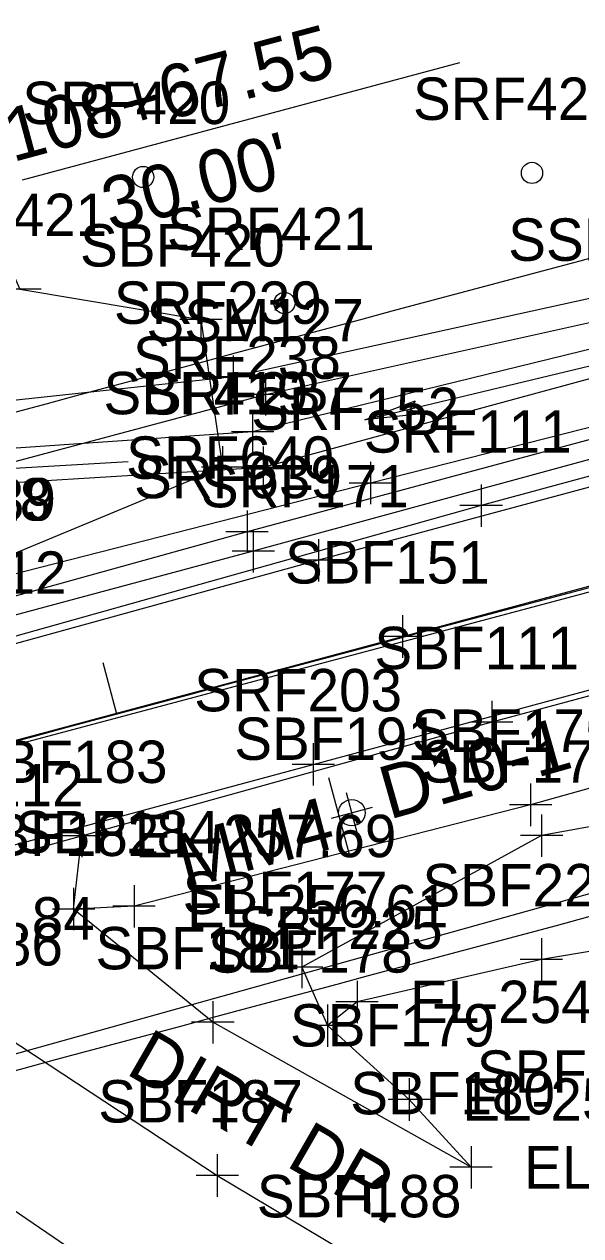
# Model space of a CAD drawing. Extents: x 818717 to 846077, y 440014 to 541392.
# Drawn here: x 831821.7 to 831874.2, y 493090.2 to 493204.5 of the extents above; entities that cross this region are included whole.
import ezdxf

# ---------------------------------------------------------------- set-up
doc = ezdxf.new("R2010")
doc.units = 0
for name, color, linetype in [('SURVEY - CENTERLINE - Preliminary', 7, 'Continuous'), ('SURVEY - CENTERLINE - Preliminary Text', 7, 'Continuous'), ('SURVEY - DRAINAGE - Area Shapes', 7, 'Continuous'), ('SURVEY - DRAINAGE - Natural Features Text', 7, 'Continuous'), ('SURVEY - DTM - Breaklines', 7, 'Continuous'), ('SURVEY - DTM - Breaklines - Points - Elevations', 7, 'Continuous'), ('SURVEY - DTM - Breaklines - Points - Locators', 7, 'Continuous'), ('SURVEY - DTM - Breaklines - Points - Numbers', 7, 'Continuous'), ('SURVEY - DTM - Spot Points - Locators', 7, 'Continuous'), ('SURVEY - DTM - Spot Points - Point Numbers', 7, 'Continuous'), ('SURVEY - PROPERTY - ROW Lines', 7, 'Continuous'), ('SURVEY - PROPERTY - Station and Offset Flags', 7, 'Continuous'), ('SURVEY - TRAFFIC CONTROL - Pavement Marking - Points - Locators', 7, 'Continuous'), ('SURVEY - TRAFFIC CONTROL - Pavement Marking - Points - Numbers', 7, 'Continuous'), ('SURVEY - TRAFFIC CONTROL - Pavement Marking with Text', 7, 'Continuous'), ('SURVEY - TRAFFIC CONTROL - Signs - Points - Locators', 7, 'Continuous'), ('SURVEY - TRAFFIC CONTROL - Signs - Points - Numbers', 7, 'Continuous'), ('SURVEY - TRAFFIC CONTROL - Signs and Devices with Text', 7, 'Continuous'), ('SURVEY - TRANSPORTATION - Features', 7, 'Continuous'), ('SURVEY - TRANSPORTATION - Features - Points - Elevations', 7, 'Continuous'), ('SURVEY - TRANSPORTATION - Features - Points - Locators', 7, 'Continuous'), ('SURVEY - TRANSPORTATION - Features - Points - Numbers', 7, 'Continuous'), ('SURVEY - TRANSPORTATION - Features Text', 7, 'Continuous'), ('SURVEY - TRANSPORTATION - Roads', 7, 'Continuous'), ('SURVEY - TRANSPORTATION - Roads - Points - Locators', 7, 'Continuous'), ('SURVEY - TRANSPORTATION - Roads - Points - Numbers', 7, 'Continuous'), ('SURVEY - UTILITIES - Electric (Overhead) with Text', 7, 'Continuous'), ('SURVEY - UTILITIES - Telephone (Underground) - Points - Locators', 7, 'Continuous'), ('SURVEY - UTILITIES - Telephone (Underground) - Points - Numbers', 7, 'Continuous'), ('SURVEY - UTILITIES - Telephone (Underground) with Text', 7, 'Continuous'), ('SURVEY - UTILITIES - Water - Points - Locators', 7, 'Continuous'), ('SURVEY - UTILITIES - Water - Points - Numbers', 7, 'Continuous'), ('SURVEY - UTILITIES - Water with Text', 7, 'Continuous'), ('SURVEY - VEGETATION - Features - Points - Locators', 7, 'Continuous'), ('SURVEY - VEGETATION - Features - Points - Numbers', 7, 'Continuous'), ('SURVEY - VEGETATION - Features with Text', 7, 'Continuous')]:
    doc.layers.add(name, color=color, linetype=linetype)

msp = doc.modelspace()

# ---------------------------------------------------------------- linework, layer by layer
at = {"layer": 'SURVEY - CENTERLINE - Preliminary'}
msp.add_arc((846074.62, 440015.93), 55000, 104.635499, 105.043654, dxfattribs=at)
msp.add_arc((846074.62, 440015.93), 55000, 104.635499, 105.043654, dxfattribs=at)
msp.add_arc((846074.62, 440015.93), 55000, 104.635499, 105.043654, dxfattribs=at)
at = {"layer": 'SURVEY - CENTERLINE - Preliminary Text'}
msp.add_line((831830.44, 493139.41), (831829.15, 493144.24), dxfattribs=at)
at = {"layer": 'SURVEY - DRAINAGE - Area Shapes'}
msp.add_lwpolyline([(833331.86, 493535.43), (832825.85, 493400.54), (832121.68, 493216.64), (831495.16, 493049.75), (830960.37, 492909.24), (830124.73, 492686.08), (830069.9, 493396.23), (830870.86, 494031.84), (831248.11, 494413.67), (831536.95, 494545.33), (832050.07, 494534.01), (832097.96, 494614.84), (832139.36, 494784.62), (832167.46, 494840.58), (832274.31, 494844.36), (832647.22, 494804.13), (832934.24, 494910.41), (833081.03, 494456.05), (833331.86, 493535.43)], dxfattribs=at)
at = {"layer": 'SURVEY - DRAINAGE - Natural Features Text'}
for p, q in [((831853.84, 493167.16), (831891.8, 493176.31)), ((831856.46, 493167.79), (831853.84, 493167.16)), ((831800.97, 493161.51), (831831.51, 493163.23))]:
    msp.add_line(p, q, dxfattribs=at)
msp.add_lwpolyline([(831853.84, 493167.16), (831858.6, 493168.97), (831858.12, 493168.19), (831858.9, 493167.71)], close=True, dxfattribs=at)
msp.add_lwpolyline([(831853.84, 493167.16), (831858.6, 493168.97), (831858.12, 493168.19), (831858.9, 493167.71), (831853.84, 493167.16)], dxfattribs=at)
at = {"layer": 'SURVEY - DTM - Breaklines'}
for points in [[(831770.96, 493123.4), (831813.86, 493135.07), (831857.39, 493146.73), (831900.86, 493158.47), (831946.48, 493170.59), (831992.71, 493182.98), (832039.15, 493195.18), (832084.76, 493206.97), (832129.99, 493218.78), (832149.29, 493223.98), (832194.39, 493235.62), (832247.61, 493249.75), (832293.49, 493261.68), (832340.52, 493273.78)], [(832142.59, 493248.12), (832139.68, 493247.54), (832108.04, 493238.25), (832059.21, 493226.8), (832016.93, 493214.13), (831977.53, 493204.88), (831934.18, 493192.82), (831885.96, 493181.02), (831841.41, 493171.23), (831796.37, 493166.38), (831801.69, 493181.68), (831795.28, 493183.83), (831789.32, 493168.76), (831775.78, 493173.56), (831765.85, 493166.76)], [(832140.22, 493244.36), (832106.95, 493233.7), (832060.11, 493221.66), (832022.66, 493211.6), (831981.44, 493201.09), (831935.37, 493189.1), (831887.47, 493176.86), (831843.25, 493166.04), (831798.12, 493162.94), (831794.2, 493164.7), (831799.41, 493178.67), (831795.65, 493181.96), (831790.41, 493167.38)], [(832140.95, 493241.96), (832107.3, 493230.3), (832060.96, 493218.28), (832023.31, 493209.39), (831981.76, 493198.9), (831936.65, 493186.2), (831888.63, 493174.71), (831844.24, 493162.67), (831795, 493159.67)], [(832140.88, 493237.3), (832107.45, 493226.49), (832065.3, 493215.2), (832029.04, 493206.5), (831988.85, 493195.72), (831947.28, 493184.33), (831903.99, 493173.8), (831854.37, 493161.21), (831813.24, 493150.7), (831784.54, 493147.95), (831766.05, 493144.17), (831768.61, 493132.98)], [(832195.49, 493218.96), (832149.66, 493208), (832104.44, 493192.76), (832056.4, 493179.89), (832008.79, 493165.69), (831963, 493154.57), (831916.73, 493144.05), (831869.5, 493130.85), (831832.06, 493121.28), (831826.36, 493121.02)], [(832151.95, 493201.02), (832107.01, 493186.71), (832059.04, 493168.48), (832010.73, 493158.07), (831966.04, 493144.93), (831919.68, 493136.81), (831870.53, 493127.95), (831847.89, 493115.55), (831850.33, 493110.02), (831858.04, 493103.05), (831863.88, 493096.65)], [(832157.93, 493179.81), (832105.79, 493168.96), (832054.16, 493155.49), (832007.33, 493148.26), (831961.05, 493132.11), (831918.6, 493124.28), (831870.52, 493116.27), (831853.11, 493112.26), (831850.33, 493110.02)]]:
    msp.add_lwpolyline(points, dxfattribs=at)
at = {"layer": 'SURVEY - DTM - Breaklines - Points - Locators'}
for p, q in [((831841.41, 493173.23), (831841.41, 493169.23)), ((831843.41, 493171.23), (831839.41, 493171.23)), ((831843.25, 493168.04), (831843.25, 493164.04)), ((831845.25, 493166.04), (831841.25, 493166.04)), ((831844.24, 493164.67), (831844.24, 493160.67)), ((831846.24, 493162.67), (831842.24, 493162.67)), ((831854.37, 493163.21), (831854.37, 493159.21)), ((831856.37, 493161.21), (831852.37, 493161.21)), ((831857.39, 493148.73), (831857.39, 493144.73)), ((831859.39, 493146.73), (831855.39, 493146.73)), ((831869.5, 493132.85), (831869.5, 493128.85)), ((831871.5, 493130.85), (831867.5, 493130.85)), ((831870.53, 493129.95), (831870.53, 493125.95)), ((831872.53, 493127.95), (831868.53, 493127.95)), ((831832.06, 493123.28), (831832.06, 493119.28)), ((831834.06, 493121.28), (831830.06, 493121.28)), ((831870.52, 493118.27), (831870.52, 493114.27)), ((831847.89, 493117.55), (831847.89, 493113.55)), ((831872.52, 493116.27), (831868.52, 493116.27)), ((831849.89, 493115.55), (831845.89, 493115.55)), ((831853.11, 493114.26), (831853.11, 493110.26)), ((831855.11, 493112.26), (831851.11, 493112.26)), ((831850.33, 493112.02), (831850.33, 493108.02)), ((831852.33, 493110.02), (831848.33, 493110.02)), ((831858.04, 493105.05), (831858.04, 493101.05)), ((831860.04, 493103.05), (831856.04, 493103.05))]:
    msp.add_line(p, q, dxfattribs=at)
at = {"layer": 'SURVEY - DTM - Spot Points - Locators'}
for centre in [(831832.92, 493190.08), (831869.63, 493190.47), (831846.26, 493178.2)]:
    msp.add_circle(centre, 1, dxfattribs=at)
at = {"layer": 'SURVEY - PROPERTY - ROW Lines'}
for radius in [55030, 54970]:
    msp.add_arc((846074.62, 440015.93), radius, 104.635499, 105.043649, dxfattribs=at)
at = {"layer": 'SURVEY - PROPERTY - Station and Offset Flags'}
msp.add_line((831862.78, 493200.87), (831821.5, 493189.78), dxfattribs=at)
msp.add_lwpolyline([(831849.39, 493073.02), (831806.89, 493102.02)], dxfattribs=at)
at = {"layer": 'SURVEY - TRAFFIC CONTROL - Pavement Marking - Points - Locators'}
for p, q in [((831849.46, 493155.92), (831849.46, 493151.92)), ((831851.46, 493153.92), (831847.46, 493153.92)), ((831848.98, 493136.67), (831848.98, 493132.67)), ((831850.98, 493134.67), (831846.98, 493134.67))]:
    msp.add_line(p, q, dxfattribs=at)
at = {"layer": 'SURVEY - TRAFFIC CONTROL - Pavement Marking with Text'}
for points in [[(832159.39, 493235.77), (832116.7, 493224.52), (832072.63, 493213.17), (832030, 493201.97), (831987.46, 493190.83), (831936.58, 493177.36), (831894.1, 493165.96), (831849.46, 493153.92), (831808.03, 493142.52), (831768.36, 493131.66), (831727.87, 493120.89), (831684.5, 493109.18), (831641.68, 493097.86), (831599.16, 493086.58), (831554.58, 493074.61), (831511.86, 493063.5), (831467.07, 493051.66), (831425.05, 493040.69), (831380.34, 493029.11), (831337.84, 493017.82), (831296.13, 493006.89), (831251.61, 492995.36), (831208.94, 492984.12), (831169.87, 492973.88)], [(831174.64, 492955.97), (831217.88, 492967.4), (831260.2, 492978.43), (831305.6, 492990.16), (831350.87, 493002.2), (831397.34, 493014.25), (831441.59, 493025.83), (831487.77, 493037.91), (831534.41, 493050.33), (831587.19, 493064.38), (831630.52, 493075.92), (831676.82, 493088.3), (831723.86, 493100.96), (831758.43, 493110.25), (831806.28, 493123.18), (831848.98, 493134.67), (831896.65, 493147.52), (831940.52, 493159.26), (831989.17, 493172.11), (832037.06, 493184.69), (832086.82, 493197.77), (832134.83, 493210.3)]]:
    msp.add_lwpolyline(points, dxfattribs=at)
at = {"layer": 'SURVEY - TRAFFIC CONTROL - Signs - Points - Locators'}
for p, q in [((831852.09, 493132.02), (831853.12, 493128.15)), ((831854.53, 493130.6), (831850.67, 493129.57))]:
    msp.add_line(p, q, dxfattribs=at)
at = {"layer": 'SURVEY - TRAFFIC CONTROL - Signs and Devices with Text'}
msp.add_line((831852.39, 493126.15), (831850.45, 493133.39), dxfattribs=at)
msp.add_circle((831852.62, 493130.11), 1.25, dxfattribs=at)
at = {"layer": 'SURVEY - TRANSPORTATION - Features'}
for points in [[(831863.88, 493096.65), (831839.5, 493110.33), (831826.36, 493121.02), (831827.14, 493127.91)], [(831798.67, 493120.14), (831817.37, 493110.69), (831839.92, 493095.88), (831854.94, 493086.93)]]:
    msp.add_lwpolyline(points, dxfattribs=at)
at = {"layer": 'SURVEY - TRANSPORTATION - Features - Points - Locators'}
for p, q in [((831827.14, 493129.91), (831827.14, 493125.91)), ((831829.14, 493127.91), (831825.14, 493127.91)), ((831826.36, 493123.02), (831826.36, 493119.02)), ((831828.36, 493121.02), (831824.36, 493121.02)), ((831839.5, 493112.33), (831839.5, 493108.33)), ((831841.5, 493110.33), (831837.5, 493110.33)), ((831863.88, 493098.65), (831863.88, 493094.65)), ((831839.92, 493097.88), (831839.92, 493093.88)), ((831865.88, 493096.65), (831861.88, 493096.65)), ((831841.92, 493095.88), (831837.92, 493095.88))]:
    msp.add_line(p, q, dxfattribs=at)
at = {"layer": 'SURVEY - TRANSPORTATION - Roads'}
for points in [[(832337.43, 493283.54), (832290.84, 493271.51), (832245.1, 493259.5), (832196.72, 493246.64), (832147.48, 493233.5), (832099.04, 493220.81), (832050.97, 493208.2), (832002.93, 493195.99), (831956.8, 493183.74), (831911.55, 493171.73), (831864.83, 493159.08), (831817.3, 493145.76), (831768.68, 493132.69)], [(832342.92, 493264.27), (832295.67, 493251.85), (832250.01, 493239.95), (832200.63, 493227.05), (832152.17, 493214.17), (832103.93, 493201.62), (832054.77, 493188.77), (832008.06, 493176.05), (831961.15, 493163.88), (831914.15, 493151.63), (831865.83, 493138.65), (831819.22, 493125.71), (831773.59, 493113.35)]]:
    msp.add_lwpolyline(points, dxfattribs=at)
at = {"layer": 'SURVEY - TRANSPORTATION - Roads - Points - Locators'}
for p, q in [((831864.83, 493161.08), (831864.83, 493157.08)), ((831866.83, 493159.08), (831862.83, 493159.08)), ((831865.83, 493140.65), (831865.83, 493136.65)), ((831867.83, 493138.65), (831863.83, 493138.65))]:
    msp.add_line(p, q, dxfattribs=at)
at = {"layer": 'SURVEY - UTILITIES - Electric (Overhead) with Text'}
msp.add_lwpolyline([(832667.18, 493331.74), (832415.28, 493266.23), (832147.85, 493195.27), (831907.96, 493131.64), (831666.03, 493064.14), (831375.19, 492986.65), (831101.3, 492913.04)], dxfattribs=at)
at = {"layer": 'SURVEY - UTILITIES - Telephone (Underground) - Points - Locators'}
for p, q in [((831842.73, 493158.61), (831842.73, 493154.61)), ((831843.31, 493156.78), (831843.31, 493152.78)), ((831844.73, 493156.61), (831840.73, 493156.61)), ((831845.31, 493154.78), (831841.31, 493154.78))]:
    msp.add_line(p, q, dxfattribs=at)
at = {"layer": 'SURVEY - UTILITIES - Telephone (Underground) with Text'}
for points in [[(832336.84, 493284.72), (832273.67, 493269.41), (832254.65, 493265.33), (832241.32, 493260.67), (832203.09, 493249.29), (832136.87, 493232.13), (832079.02, 493217.89), (831981.8, 493192.44), (831904.38, 493171.41), (831843.31, 493154.78), (831799.38, 493142.99), (831790.74, 493148.24), (831757.75, 493149.99)], [(832214.24, 493268.88), (832214.09, 493255.37), (832202.72, 493250.84), (832136.43, 493233.69), (832079.13, 493219.64), (831981.43, 493194.27), (831903.88, 493173.04), (831842.73, 493156.61), (831799.25, 493144.57), (831792.09, 493149.13), (831757.2, 493152.41)]]:
    msp.add_lwpolyline(points, dxfattribs=at)
at = {"layer": 'SURVEY - UTILITIES - Water - Points - Locators'}
for p, q in [((831844.47, 493171.57), (831844.47, 493167.57)), ((831846.47, 493169.57), (831842.47, 493169.57))]:
    msp.add_line(p, q, dxfattribs=at)
at = {"layer": 'SURVEY - UTILITIES - Water with Text'}
msp.add_lwpolyline([(831168.53, 492982.83), (831221.68, 492997.59), (831271.35, 493010.03), (831320.05, 493023.02), (831382.11, 493039.09), (831464.43, 493059.02), (831521.6, 493075.98), (831637.27, 493105.47), (831699.54, 493130.69), (831734.63, 493142.29), (831763.92, 493149.4), (831800.53, 493157.83), (831844.47, 493169.57), (831878.73, 493177.18), (831933.72, 493193.59), (832000.95, 493211.25), (832058.59, 493225.48), (832113.6, 493238.29), (832172.68, 493261.93), (832217.98, 493273.66), (832269.17, 493287.2), (832330.79, 493299.45)], dxfattribs=at)
at = {"layer": 'SURVEY - VEGETATION - Features - Points - Locators'}
for p, q in [((831823.29, 493179.51), (831819.29, 493179.51)), ((831838.37, 493178.64), (831838.37, 493174.64)), ((831840.37, 493176.64), (831836.37, 493176.64)), ((831840.42, 493164.7), (831840.42, 493160.7)), ((831842.42, 493162.7), (831838.42, 493162.7))]:
    msp.add_line(p, q, dxfattribs=at)
at = {"layer": 'SURVEY - VEGETATION - Features with Text'}
msp.add_lwpolyline([(832074.38, 493372.96), (832067.41, 493358.76), (832023.76, 493337.86), (831986.44, 493318.14), (831942.76, 493297.45), (831897.19, 493279.57), (831855.2, 493264.73), (831811.79, 493246.68), (831803.11, 493234.77), (831807.59, 493210.38), (831821.29, 493179.51), (831838.37, 493176.64), (831840.42, 493162.7), (831816.2, 493152.67), (831768.47, 493143.37), (831736.25, 493132.08), (831689.16, 493118.85), (831643.12, 493105.66), (831600.48, 493097.11)], dxfattribs=at)

# ---------------------------------------------------------------- texts
at = {"layer": 'SURVEY - DTM - Breaklines - Points - Elevations'}
for s, p in [('EL-250.39', (831800, 493157.67)), ('EL-256.61', (831837.06, 493119.28)), ('EL-254.15', (831858.11, 493110.26)), ('EL-252.84', (831863.04, 493101.05))]:
    msp.add_text(s, height=4, dxfattribs=at).set_placement(p)
at = {"layer": 'SURVEY - DTM - Breaklines - Points - Numbers'}
for s, p in [('SRF239', (831830.16, 493176.23)), ('SRF238', (831831.96, 493171.04)), ('SRF237', (831833, 493167.67)), ('SRF152', (831843.13, 493166.21)), ('SBF151', (831846.31, 493151.73)), ('SBF175', (831858.26, 493135.85)), ('SBF176', (831859.18, 493132.95)), ('SBF184', (831820.82, 493126.28)), ('SBF224', (831859.28, 493121.27)), ('SBF177', (831836.65, 493120.55)), ('SBF225', (831841.87, 493117.26)), ('SBF178', (831839.04, 493115.02)), ('SBF179', (831846.78, 493108.05))]:
    msp.add_text(s, height=4, dxfattribs=at).set_placement(p)
at = {"layer": 'SURVEY - DTM - Spot Points - Point Numbers'}
for s, p in [('SRF420', (831821.51, 493195.08)), ('SRF422', (831858.39, 493195.47)), ('SRF421', (831835.17, 493183.2)), ('SBF223', (831864.41, 493103.68))]:
    msp.add_text(s, height=4, dxfattribs=at).set_placement(p)
at = {"layer": 'SURVEY - PROPERTY - Station and Offset Flags'}
for s, p in [('108+67.55', (831820.6, 493191.47)), ("30.00'", (831829.86, 493184.9))]:
    msp.add_text(s, height=5, rotation=15.0436, dxfattribs=at).set_placement(p)
at = {"layer": 'SURVEY - TRAFFIC CONTROL - Pavement Marking - Points - Numbers'}
for s, p in [('SRF171', (831838.37, 493158.92)), ('SRF203', (831837.74, 493139.67))]:
    msp.add_text(s, height=4, dxfattribs=at).set_placement(p)
at = {"layer": 'SURVEY - TRAFFIC CONTROL - Signs - Points - Numbers'}
msp.add_text('SBF191', height=4, dxfattribs=at).set_placement((831841.52, 493135.09))
at = {"layer": 'SURVEY - TRAFFIC CONTROL - Signs and Devices with Text'}
for s, rotation, p in [('D10-1', 15.8555, (831856.14, 493129.44)), ('MM4', 14.8059, (831836.91, 493123.05))]:
    msp.add_text(s, height=5, rotation=rotation, dxfattribs=at).set_placement(p)
at = {"layer": 'SURVEY - TRANSPORTATION - Features - Points - Elevations'}
for s, p in [('EL-257.69', (831832.14, 493125.91)), ('EL-257.84', (831803.67, 493118.14)), ('EL-252.14', (831868.88, 493094.65))]:
    msp.add_text(s, height=4, dxfattribs=at).set_placement(p)
at = {"layer": 'SURVEY - TRANSPORTATION - Features - Points - Numbers'}
for s, p in [('SBF183', (831815.9, 493132.91)), ('SBF182', (831815.12, 493126.02)), ('SBF186', (831806.02, 493115.69)), ('SBF181', (831828.42, 493115.33)), ('SBF180', (831852.47, 493101.65)), ('SBF187', (831828.68, 493100.88)), ('SBF188', (831843.65, 493091.93))]:
    msp.add_text(s, height=4, dxfattribs=at).set_placement(p)
at = {"layer": 'SURVEY - TRANSPORTATION - Features Text'}
msp.add_text('DIRT DR.', height=5, rotation=330.0659, dxfattribs=at).set_placement((831831.15, 493105.54))
at = {"layer": 'SURVEY - TRANSPORTATION - Roads - Points - Numbers'}
for s, p in [('SRF111', (831853.75, 493164.08)), ('SRF112', (831806.06, 493150.76)), ('SBF111', (831854.75, 493143.65)), ('SBF112', (831807.98, 493130.71))]:
    msp.add_text(s, height=4, dxfattribs=at).set_placement(p)
at = {"layer": 'SURVEY - UTILITIES - Telephone (Underground) - Points - Numbers'}
for s, p in [('SRF640', (831831.31, 493161.61)), ('SRF639', (831832.06, 493159.78))]:
    msp.add_text(s, height=4, dxfattribs=at).set_placement(p)
at = {"layer": 'SURVEY - UTILITIES - Water - Points - Numbers'}
for s, p in [('SSM126', (831867.38, 493182.18)), ('SSM127', (831833.23, 493174.57))]:
    msp.add_text(s, height=4, dxfattribs=at).set_placement(p)
at = {"layer": 'SURVEY - VEGETATION - Features - Points - Numbers'}
for s, p in [('SBF421', (831810.2, 493184.51)), ('SBF420', (831826.96, 493181.64)), ('SBF419', (831829.17, 493167.7)), ('SBF418', (831804.91, 493157.67))]:
    msp.add_text(s, height=4, dxfattribs=at).set_placement(p)

doc.saveas('drawing.dxf')
